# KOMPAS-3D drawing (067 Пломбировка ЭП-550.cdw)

Referenced files in \\Promsrv4\спо\002_Проекты (ПСПД)\г. Южно-Сахалинск\Работы по ИТП (COWI) 2014\ПРОЕКТЫ ИТП\Украинская, 9\пломбировка приборов\: Пломбировка ЭП-550.cdw
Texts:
  ПСПД-0000-2015
  Схема пломбировки Преобразователя расхода ЭМИР-ПРАМЕР-550
  пломба
  Место под пломбу
  для пломбы использовать мастику
  пломбировочную термостойкую по ГОСТ 18680-73
  Стандартные изделия
  Прокладка А-15-16-ПОН ГОСТ 15180-86
  Гайка М12-6H (S18) ГОСТ 5915-70
  Прокладка
  ГОСТ 15180-86
  А-15-16-ПОН
  Фланец 1-15-16 Ст3сп ГОСТ 12820-80
  Фланец
  ГОСТ 12820-80
  Схема пломбировки Преобразователя
  расхода ЭМИР-ПРАМЕР-550
  ПСПД-0093-2014-
  ЗАО "ПромСервис"
Dimensions and other numbers on the sheet: 15180_86.vbs; 1-15-16 Ст3сп; 1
